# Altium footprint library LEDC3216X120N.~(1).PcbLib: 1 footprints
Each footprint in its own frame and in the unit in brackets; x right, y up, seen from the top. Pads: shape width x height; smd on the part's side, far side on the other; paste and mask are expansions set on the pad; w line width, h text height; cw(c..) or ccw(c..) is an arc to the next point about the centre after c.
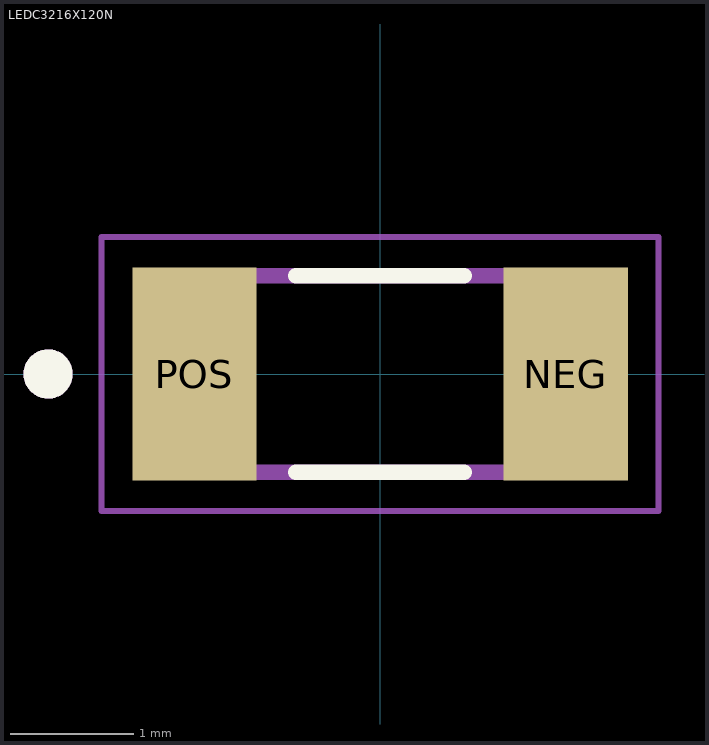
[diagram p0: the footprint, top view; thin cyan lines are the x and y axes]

## LEDC3216X120N [mm]
pads (2):
  rect 1.01x1.73 smd: NEG(1.51,0) POS(-1.51,0)
Top Overlay:
  circle w0.2: c-2.7,0 r0.1
  lines w0.127: -0.685,-0.8 0.685,-0.8 ; -0.685,0.8 0.685,0.8
Mechanical 13:
  circle w0.2: c-2.7,0 r0.1
  lines w0.127: -1.6,-0.8 -1.6,0.8 1.6,0.8 1.6,-0.8 -1.6,-0.8
Mechanical 15:
  lines w0.05: -2.265,-1.115 -2.265,1.115 2.265,1.115 2.265,-1.115 -2.265,-1.115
